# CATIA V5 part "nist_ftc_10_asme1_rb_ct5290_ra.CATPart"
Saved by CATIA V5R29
Part number: nist_ftc_10_asme1
Nomenclature: nist_ftc_10_asme1
Source: Unknown
Bounding box of the stored display mesh (mm): x -79 to 79, y 0 to 31, z -37.5 to 37.5
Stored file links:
  E:\users\dgn\TPS V5\Import-export annotations\Step\PMI representation 2015\NIST UC\FTC\R29\nist_ftc_10_asme1_rb - V5R29.CATPart
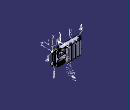
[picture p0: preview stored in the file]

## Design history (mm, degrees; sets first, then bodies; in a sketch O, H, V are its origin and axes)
TTRSSet1
f4a2d38f3ddc11d3a929006094b99c4b_11 "CATTPSSet"
Set1 "MBD_ABCDE"
  AxisSystem1 "ABC": origin (70, 0, 28.5), X (0, 0, 1), Y (-140, 0, 0), Z (0, -1, 0)
Set2 "MBD_B"
  AxisSystem2 "AJ": origin (47.5, 0, 37.5), X (1, 0, 0), Y (0, 1, 0), Z (0, 0, 1)
  Line1: stored without definition
  Line2: type PtDir, Direction face of Solid1, Start 15, End 27, RefPoint {point type OnCurve, Support edge [face of Solid1 | face of Solid1], Ratio 0.5}
  Extract1: ExtractElem face of Solid1
  Extract2: ExtractElem face of Solid1
  Join1: Elements (Extract2; Extract1), ElementsToFederate (face of Solid1; face of Solid1)
  Plane1: type Offset, RefPlane face of Solid1, Offset -2, reversed
  Split1: ToCut Join1, Cutting Plane1
  AxisLine1: Element face of Solid1
  Plane2: type Offset, RefPlane face of Solid1, Offset 0, reversed
  Intersect1: ToIntersect1 AxisLine1, ToIntersect2 Plane2
  AxisSystem3 "DE-F-G": origin (44.5, 27, -25), X (0, 0, -1), Y (-11, 0, 0), Z (0, 1, 0)
  AxisLine2: Element face of Solid1
  Plane3: type Offset, RefPlane face of Solid1, Offset 0, reversed
  Intersect2: ToIntersect1 AxisLine2, ToIntersect2 Plane3
  AxisSystem4 "H": origin (61.7906, 31, 23.5), X (-0.0379, 0, -0.9993), Y (-0.9993, 0, 0.0379), Z (0, 1, 0)
Set3 "MBD_C"
  Extract3: ExtractElem face of Solid1
  Extract4: ExtractElem face of Solid1
  Join2: Elements (Extract3; Extract4), ElementsToFederate (face of Solid1; face of Solid1)
  Split2: ToCut Join2, Cutting Plane1
  AxisSystem5 "DBC": origin (44.5, 27, -25), X (0, 0, -1), Y (-1, 0, 0), Z (0, 1, 0)
  AxisSystem6 "HKL": origin (61.7906, 31, 23.5), X (0, 0, -1), Y (-28.5811, 0, 0), Z (0, 1, 0)
Set4 "MBD_D"
  Sketch1 on face of Solid1, origin (0, 31, 0), H (-1, 0, 0), V (0, 0, 1)
    reference projected arc E1 centre (-52, 23.5) radius 7.5 from (-52, 31) to (-52, 16) ccw from edge [face of Solid1 | face of Solid1]
    point P1 (-52, 31)
    point P2 (-52, 16)
    reference projected arc E2 centre (-43, 23.5) radius 7.5 from (-43, 16) to (-43, 31) ccw from edge [face of Solid1 | face of Solid1]
    point P3 (-43, 16)
    point P4 (-43, 31)
    point P5 (-52.0003, 23.5)
    line L1 (-61.7906, 23.5) -> (-55.4543, 31.0513)
    point P6 (-61.7906, 23.5)
    point P8 (-43, 23.5)
    construction line L2 (-62, 23.5) -> (-31, 23.5)
    line L3 (-61.7906, 23.5) -> (-55.4543, 15.9487)
    point P13 (-33.2094, 23.5)
    line L4 (-33.2094, 23.5) -> (-39.5459, 31.0515)
    line L5 (-33.2094, 23.5) -> (-39.5839, 15.9032)
    radius E1 = 7.5 (reference)
    distance P5 P1 = 7.5
    distance P5 P2 = 7.5
    distance P8 P4 = 7.5
    distance P8 P3 = 7.5
    distance L2 P8 = 0
    angle L1 L3 = 100
    angle L4 L5 = 100
    horizontal: L2 H
    coincidence: P6 L2, P13 L2
    tangency: E1 L1, L3 E1, E2 L4, L5 E2
  Extrude1: Lim1 7, Lim2 0, Element1 Sketch1
  AxisSystem7 "HKL": origin (61.7906, 31, 23.5), X (0, 0, -1), Y (-28.5811, 0, 0), Z (0, 1, 0)
  Extract5: ExtractElem face of Solid1
  Intersect3: ToIntersect1 Extrude1, ToIntersect2 Extract5
  Extract6: ExtractElem face of Solid1
  Intersect4: ToIntersect1 Extract6, ToIntersect2 Extrude1
  AxisSystem8 "DEB": origin (33.5, 27, -25), X (-0.0379, 0, -0.9993), Y (-0.9993, 0, 0.0379), Z (0, 1, 0)
  AxisSystem9 "DFB": origin (44.5, 27, -25), X (-0.0379, 0, -0.9993), Y (-0.9993, 0, 0.0379), Z (0, 1, 0)
  AxisSystem10 "DGB": origin (55.5, 27, -25), X (-0.0379, 0, -0.9993), Y (-0.9993, 0, 0.0379), Z (0, 1, 0)
Body1 "Solid1" (main body)
  Solid1: solid without history
  Thread1: "M3", diameter 3, depth 10, pitch 0.5, on face of Solid1, from face of Solid1
  Thread2: "M3", diameter 3, depth 10, pitch 0.5, on face of Solid1, from face of Solid1
  Thread3: "M3", diameter 3, depth 10, pitch 0.5, on face of Solid1, from face of Solid1
  Thread4: "M3", diameter 3, depth 10, pitch 0.5, on face of Solid1, from face of Solid1
  Thread5: "M3", diameter 3, depth 10, pitch 0.5, on face of Solid1, from face of Solid1
  Thread6: "M3", diameter 3, depth 10, pitch 0.5, on face of Solid1, from face of Solid1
